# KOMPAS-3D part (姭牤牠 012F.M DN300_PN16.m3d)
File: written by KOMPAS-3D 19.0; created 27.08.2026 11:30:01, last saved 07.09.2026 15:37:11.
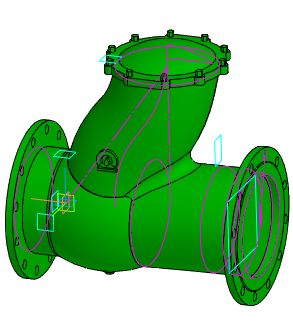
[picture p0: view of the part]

Document properties: Автор: Энергия; Полное имя файла: Z:\3.Личные\kachalov\001_3d для проектировщиков\х.х Тип 012F\012F.M\Клапан 012F.M DN300_PN16.m3d

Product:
- Part/product: (unnamed)  | designation Клапан 012F.M DN300_PN16
    Масса: 303.516

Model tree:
1. Эскиз:1
2. Элемент вращения:1
     Угол 1 = 360
3. Эскиз:2  (with: Элемент вращения:1)
4. Параллельная плоскость:3
5. Эскиз:26
6. Смещенная плоскость:5
     Расстояние = 150
7. Элемент по траектории:1
     Толщина стенки 1 = 1
8. Эскиз:31
9. Эскиз:38  (with: Элемент вращения:1)
10. Параллельная плоскость:4
11. Смещенная плоскость:2  (with: Элемент вращения:1)
     Расстояние = 32
12. Эскиз:39  (with: Элемент вращения:1)
13. Эскиз:40  (with: Элемент вращения:1)
14. Смещенная плоскость:3
     Расстояние = 33
15. Эскиз:42  (with: Элемент вращения:1)
16. Элемент по сечениям:4
17. Элемент вращения:6  (with: Элемент вращения:1)
     Угол 1 = 360
18. Эскиз:10  (with: Элемент вращения:1)
19. Элемент выдавливания:3  (with: Элемент вращения:1)
     Расстояние 2 = 22
20. Массив по концентрической сетке:1  (with: Элемент выдавливания:3, Эскиз:10, Элемент вращения:1)  (12 pattern instances)
     Шаг 2 = 360
21. Эскиз:11  (with: Элемент вращения:1)
22. Элемент выдавливания:4  (with: Элемент вращения:1)
23. Массив по концентрической сетке:2  (with: Элемент выдавливания:4, Эскиз:11, Элемент вращения:1)  (12 pattern instances)
     Шаг 2 = 360
24. Эскиз:32
25. Элемент выдавливания:13
     Расстояние 1 = 25
26. Эскиз:33  (with: Элемент выдавливания:13)
27. Элемент вращения:7
     Угол 1 = 360
28. Эскиз:34  (with: Элемент вращения:1, Элемент вращения:6)
29. Элемент выдавливания:14  (with: Элемент вращения:6)
     Расстояние 1 = 190; Смещение 1 = 10
30. Скругление:23  (with: Элемент выдавливания:14)
     Радиус = 3
31. Эскиз:35  (with: Элемент выдавливания:14)
32. Элемент выдавливания:15
     Расстояние 1 = 10
33. Эскиз:36  (with: Элемент выдавливания:13)
34. Элемент выдавливания:16
     Расстояние 1 = 15
35. Эскиз:43  (with: Элемент выдавливания:13)
36. Массив по концентрической сетке:3  (with: Элемент выдавливания:16, Эскиз:36, Эскиз:33)  (10 pattern instances)
     Шаг 2 = 360
37. Смещенная плоскость:4
     Расстояние = 160
38. Эскиз:46
39. Элемент выдавливания:20  (with: Элемент по траектории:1)
     Расстояние 2 = 9.21632
40. Эскиз:47  (with: Элемент вращения:1)
41. Эскиз:48  (with: Элемент вращения:1)
42. Элемент выдавливания:22
     Расстояние 2 = 360
43. Эскиз:49  (with: Элемент вращения:1)
44. Скругление:28  (with: Элемент по сечениям:4)
     Радиус = 30
45. Скругление:29  (with: Элемент вращения:6)
     Радиус = 20

Expressions: Dn/2; D/2; D2/2; 360/(2*n); 360/(n*2); D3/2
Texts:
  Клапан 012F.M DN300_PN16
